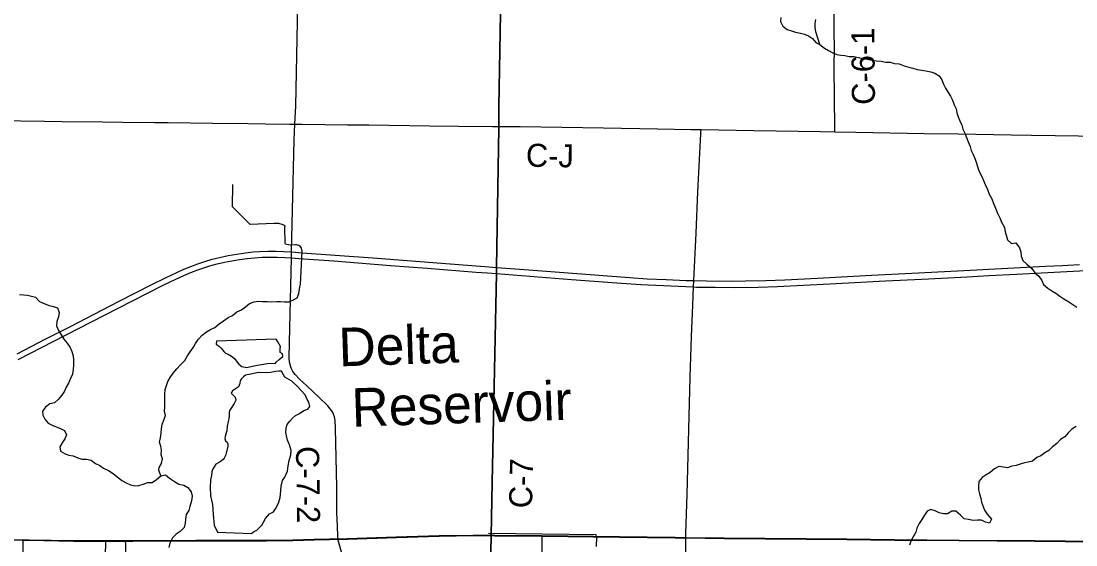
# Model space of a CAD drawing. Extents: x -21.7 to 34, y 0 to 22.
# Drawn here: x 26.522 to 29.12, y 18.47 to 19.76 of the extents above; entities that cross this region are included whole.
import ezdxf

# ---------------------------------------------------------------- set-up
doc = ezdxf.new("R2010")
doc.units = 0
for name, color, linetype in [('GM_X_Corporation', 7, 'Continuous'), ('GM_X_County_Road', 7, 'Continuous'), ('GM_X_County_Road_Text', 7, 'Continuous'), ('GM_X_Interchange_Ramps', 7, 'Continuous'), ('GM_X_Interstate_Route', 7, 'Continuous'), ('GM_X_Minor_Lake', 7, 'Continuous'), ('GM_X_Minor_Lake_Text', 7, 'Continuous'), ('GM_X_Minor_River', 7, 'Continuous'), ('GM_X_Township_Road', 7, 'Continuous')]:
    doc.layers.add(name, color=color, linetype=linetype)

msp = doc.modelspace()

# ---------------------------------------------------------------- linework, layer by layer
at = {"layer": 'GM_X_Corporation'}
for points in [[(26.5248, 17.9802), (26.527, 18.482), (26.7301, 18.4797), (26.7284, 18.4023)], [(27.6767, 18.3342), (27.6799, 18.4934), (27.8047, 18.4919), (27.804, 17.9866)]]:
    msp.add_lwpolyline(points, dxfattribs=at)
at = {"layer": 'GM_X_County_Road'}
for p, q in [((26.7303, 18.4792), (26.7798, 18.4794)), ((27.6769, 18.3336), (27.6801, 18.4929))]:
    msp.add_line(p, q, dxfattribs=at)
for points in [[(27.1963, 19.5062), (27.1964, 19.5073), (27.1988, 19.5508), (27.2033, 19.7591), (27.207, 19.9519), (27.2091, 20.0793), (27.2101, 20.2006), (27.2118, 20.3219), (27.2128, 20.4245), (27.2137, 20.5022), (27.2139, 20.5158)], [(27.6992, 19.5006), (27.6996, 19.5488), (27.7037, 19.7788), (27.7084, 20.0054), (27.7128, 20.2943), (27.7149, 20.4186), (27.7159, 20.4621), (27.717, 20.4952)], [(28.5268, 19.4873), (28.5267, 19.4976), (28.5254, 19.6466), (28.5254, 19.6682), (28.5255, 19.6736), (28.5238, 19.8343), (28.5233, 19.9152), (28.5215, 20.1238), (28.5203, 20.2794), (28.52, 20.376), (28.5193, 20.4694), (28.5191, 20.4734), (28.519, 20.4796), (28.5189, 20.4807)], [(26.433, 19.5159), (26.4618, 19.5156), (26.5799, 19.5136), (26.6235, 19.5132), (26.723, 19.5118), (26.7727, 19.5112), (26.8505, 19.5102), (26.8847, 19.51), (26.9935, 19.509), (27.0806, 19.5079), (27.1241, 19.5072), (27.1832, 19.5062), (27.1963, 19.5062)], [(27.3033, 18.4837), (27.3023, 18.491), (27.3016, 18.5158), (27.3002, 18.5499), (27.3001, 18.5622), (27.2996, 18.6119), (27.2965, 18.7577), (27.2957, 18.7764), (27.294, 18.7858), (27.292, 18.7917), (27.2893, 18.7974), (27.2839, 18.8052), (27.2777, 18.8123), (27.2554, 18.834), (27.2257, 18.8615), (27.2076, 18.8785), (27.197, 18.8897), (27.1916, 18.8971), (27.1874, 18.9053), (27.1855, 18.9111), (27.1836, 18.9201), (27.1829, 18.9324), (27.1841, 19.0039), (27.188, 19.1769), (27.1883, 19.1917), (27.1945, 19.4669), (27.1963, 19.5062)], [(27.1963, 19.5062), (27.2143, 19.506), (27.3262, 19.505), (27.379, 19.5043), (27.4288, 19.5038), (27.5283, 19.5024), (27.5998, 19.5016), (27.6838, 19.5008), (27.6992, 19.5006)], [(27.6801, 18.4929), (27.6827, 18.6228), (27.6932, 19.1383), (27.6935, 19.1534), (27.6992, 19.496), (27.6992, 19.5006)], [(27.6992, 19.5006), (27.7084, 19.5006), (27.7519, 19.5003), (27.9571, 19.497), (28.0907, 19.4945), (28.1716, 19.4934), (28.197, 19.4929)], [(28.1596, 18.4872), (28.1599, 18.4982), (28.1625, 18.5945), (28.1704, 18.8835), (28.1732, 18.983), (28.1766, 19.0605), (28.1787, 19.1054), (28.1794, 19.1211), (28.1848, 19.2375), (28.1895, 19.34), (28.1963, 19.4828), (28.1965, 19.4859), (28.197, 19.4929)], [(28.197, 19.4929), (28.327, 19.4906), (28.4917, 19.4879), (28.5268, 19.4873)], [(28.5268, 19.4873), (28.5787, 19.4865), (28.7466, 19.4836), (28.8305, 19.4824), (28.874, 19.4815), (28.9611, 19.4803), (29.0108, 19.4795), (29.1849, 19.4765), (29.2037, 19.4762)], [(26.4146, 18.4834), (26.4771, 18.4821), (26.5273, 18.4815)], [(26.5273, 18.4815), (26.5424, 18.4813), (26.6512, 18.4792), (26.7009, 18.479), (26.7303, 18.4792)], [(26.7798, 18.4794), (26.7972, 18.4795), (26.9526, 18.4799), (27.0334, 18.4801), (27.0738, 18.4802), (27.1266, 18.4803), (27.1919, 18.4811), (27.2447, 18.4823), (27.282, 18.4832), (27.3033, 18.4837)], [(26.7819, 18.4023), (26.7817, 18.422), (26.7811, 18.4344), (26.78, 18.4717), (26.7798, 18.4794)], [(27.3033, 18.4837), (27.3255, 18.4841), (27.4467, 18.4882), (27.5523, 18.4917), (27.6363, 18.4929), (27.6614, 18.4928), (27.6801, 18.4929)], [(27.3679, 18.2386), (27.3675, 18.2406), (27.3653, 18.2495), (27.3596, 18.2701), (27.3507, 18.3034), (27.3474, 18.3166), (27.3328, 18.3708), (27.3094, 18.4578), (27.3036, 18.4819), (27.3033, 18.4837)], [(27.6801, 18.4929), (27.6889, 18.4927), (27.8049, 18.4914)], [(27.8049, 18.4914), (27.9966, 18.4892), (28.1334, 18.4875), (28.1596, 18.4872)], [(28.153, 17.9846), (28.1531, 17.9926), (28.1537, 18.0454), (28.155, 18.1199), (28.1556, 18.1758), (28.1574, 18.3094), (28.1597, 18.474), (28.1596, 18.4872)], [(28.1596, 18.4872), (28.2546, 18.4861), (28.5561, 18.4831), (28.6742, 18.4819), (28.8328, 18.4806), (29.0193, 18.4793), (29.1704, 18.4779)]]:
    msp.add_lwpolyline(points, dxfattribs=at)
at = {"layer": 'GM_X_Interchange_Ramps'}
for points in [[(26.4769, 18.4826), (26.527, 18.482), (26.5421, 18.4818), (26.6509, 18.4797), (26.7006, 18.4796), (26.7301, 18.4797), (26.7796, 18.4799), (26.797, 18.48), (26.9524, 18.4805), (27.0332, 18.4807), (27.0736, 18.4808), (27.1264, 18.4808), (27.1917, 18.4817), (27.2445, 18.4829), (27.2818, 18.4838), (27.3031, 18.4842), (27.3253, 18.4846), (27.4464, 18.4887), (27.5521, 18.4922), (27.636, 18.4934), (27.6611, 18.4934), (27.6799, 18.4934), (27.6824, 18.6234), (27.6929, 19.1388), (27.6932, 19.154), (27.6989, 19.4965), (27.699, 19.5012), (27.6994, 19.5494), (27.7034, 19.7794)], [(27.7034, 19.7794), (27.6994, 19.5494), (27.699, 19.5012), (27.6989, 19.4965), (27.6932, 19.154), (27.6929, 19.1388), (27.6824, 18.6234), (27.6799, 18.4934), (27.6887, 18.4933), (27.8047, 18.4919), (27.9964, 18.4897), (28.1332, 18.488), (28.1594, 18.4877), (28.2544, 18.4866), (28.5559, 18.4837), (28.674, 18.4825), (28.8325, 18.4812), (29.019, 18.4799), (29.1702, 18.4785)], [(27.6767, 18.3342), (27.6799, 18.4934), (27.6611, 18.4934), (27.636, 18.4934), (27.5521, 18.4922), (27.4464, 18.4887), (27.3253, 18.4846), (27.3031, 18.4842), (27.2818, 18.4838), (27.2445, 18.4829), (27.1917, 18.4817), (27.1264, 18.4808), (27.0736, 18.4808), (27.0332, 18.4807), (26.9524, 18.4805), (26.797, 18.48), (26.7796, 18.4799), (26.7301, 18.4797), (26.7006, 18.4796), (26.6509, 18.4797), (26.5421, 18.4818), (26.527, 18.482), (26.4769, 18.4826)], [(29.1702, 18.4785), (29.019, 18.4799), (28.8325, 18.4812), (28.674, 18.4825), (28.5559, 18.4837), (28.2544, 18.4866), (28.1594, 18.4877), (28.1332, 18.488), (27.9964, 18.4897), (27.8047, 18.4919), (27.6887, 18.4933), (27.6799, 18.4934), (27.6767, 18.3342)]]:
    msp.add_lwpolyline(points, dxfattribs=at)
at = {"layer": 'GM_X_Interstate_Route'}
for points in [[(26.5123, 18.9409), (26.5814, 18.9765), (26.6425, 19.0074), (26.7642, 19.0699), (26.8444, 19.1111), (26.8777, 19.1278), (26.9058, 19.1412), (26.9228, 19.1488), (26.94, 19.1559), (26.9575, 19.1624), (26.9752, 19.1682), (26.9931, 19.1734), (27.0111, 19.178), (27.0323, 19.1826), (27.0537, 19.1864), (27.0752, 19.1895), (27.0938, 19.1915), (27.1092, 19.1926), (27.131, 19.1934), (27.1496, 19.1935), (27.1682, 19.193), (27.1868, 19.1918), (27.1883, 19.1917), (27.2146, 19.1895), (27.3883, 19.1768), (27.5681, 19.163), (27.6642, 19.1556), (27.6935, 19.1534), (27.7727, 19.1476), (28.0208, 19.1285), (28.0642, 19.1257), (28.1108, 19.1233), (28.1605, 19.1215), (28.1794, 19.1211), (28.2103, 19.1204), (28.2756, 19.1199), (28.3067, 19.1202), (28.3565, 19.1214), (28.4031, 19.1231), (28.4838, 19.1271), (28.6173, 19.1346), (28.7167, 19.1392), (28.8285, 19.1451), (28.9682, 19.1522), (29.0459, 19.1562), (29.0862, 19.1585), (29.1297, 19.1605)], [(26.5154, 18.9264), (26.6314, 18.9863), (26.7616, 19.0528), (26.8723, 19.1094), (26.903, 19.1246), (26.9228, 19.1337), (26.94, 19.1409), (26.9575, 19.1476), (26.9723, 19.1526), (26.9872, 19.1572), (27.0052, 19.162), (27.0234, 19.1663), (27.0417, 19.17), (27.0601, 19.1731), (27.0787, 19.1755), (27.0973, 19.1773), (27.1159, 19.1784), (27.1346, 19.1788), (27.1533, 19.1786), (27.172, 19.1779), (27.188, 19.1769), (27.2061, 19.1757), (27.2929, 19.1694), (27.4324, 19.1583), (27.5223, 19.1516), (27.6432, 19.1421), (27.6711, 19.14), (27.6932, 19.1383), (27.8779, 19.124), (27.9897, 19.1154), (28.0488, 19.111), (28.1787, 19.1054), (28.1858, 19.1051), (28.2318, 19.1048), (28.2786, 19.1039), (28.3377, 19.1049), (28.3843, 19.1063), (28.5147, 19.1128), (28.6513, 19.1201), (28.7413, 19.1247), (28.8531, 19.1304), (28.9059, 19.1332), (28.9742, 19.1365), (29.0829, 19.1422), (29.191, 19.148)]]:
    msp.add_lwpolyline(points, dxfattribs=at)
at = {"layer": 'GM_X_Minor_Lake'}
for p, q in [((27.1507, 18.9763), (27.0034, 18.9716)), ((27.0064, 18.5013), (27.0898, 18.4982))]:
    msp.add_line(p, q, dxfattribs=at)
for points in [[(27.0034, 18.9716), (27.0029, 18.9648), (27.0062, 18.9617), (27.0111, 18.9589), (27.0148, 18.9543), (27.0181, 18.9508), (27.0218, 18.9466), (27.0255, 18.9419), (27.0319, 18.9399), (27.0409, 18.9351), (27.0476, 18.9289), (27.052, 18.9231), (27.0582, 18.9154), (27.0661, 18.9095), (27.0782, 18.9073), (27.0953, 18.9111), (27.1285, 18.9165), (27.1486, 18.9179), (27.1502, 18.9198), (27.1583, 18.9268), (27.1668, 18.9338), (27.1658, 18.9407), (27.1606, 18.9442), (27.1601, 18.9533), (27.161, 18.9586), (27.1581, 18.9648), (27.1544, 18.9705), (27.1507, 18.9763)], [(27.0898, 18.4982), (27.0948, 18.5023), (27.1025, 18.5063), (27.1087, 18.5119), (27.1149, 18.5182), (27.1196, 18.5257), (27.124, 18.5347), (27.1345, 18.5466), (27.1441, 18.5517), (27.1492, 18.5584), (27.1564, 18.5731), (27.1601, 18.5866), (27.1617, 18.6037), (27.1631, 18.6147), (27.1664, 18.6283), (27.1719, 18.6369), (27.1788, 18.6519), (27.1802, 18.6648), (27.1828, 18.6776), (27.1869, 18.6916), (27.1875, 18.7022), (27.1833, 18.7163), (27.1786, 18.7278), (27.1762, 18.7389), (27.1742, 18.748), (27.1752, 18.7583), (27.178, 18.7662), (27.1843, 18.7751), (27.1906, 18.7822), (27.1979, 18.7885), (27.2083, 18.794), (27.2187, 18.8006), (27.2283, 18.8045), (27.2337, 18.8109), (27.2313, 18.8219), (27.2269, 18.8285), (27.2219, 18.8396), (27.2123, 18.8504), (27.2038, 18.8597), (27.1893, 18.873), (27.1777, 18.8801), (27.1717, 18.8832), (27.1688, 18.8886), (27.1633, 18.8975), (27.1572, 18.8983), (27.1496, 18.8974), (27.1367, 18.895), (27.1245, 18.8941), (27.1067, 18.8942), (27.0884, 18.8904), (27.0747, 18.8884), (27.0704, 18.8843), (27.0646, 18.878), (27.0618, 18.8739), (27.0609, 18.8679), (27.0593, 18.8637), (27.0581, 18.8592), (27.0527, 18.8563), (27.043, 18.8497), (27.0399, 18.844), (27.0447, 18.8386), (27.0499, 18.8339), (27.0512, 18.8263), (27.0468, 18.8181), (27.0394, 18.8065), (27.0354, 18.8012), (27.0349, 18.7956), (27.0344, 18.7876), (27.0342, 18.7804), (27.0321, 18.7736), (27.0296, 18.7627), (27.0289, 18.7509), (27.0277, 18.746), (27.0248, 18.7369), (27.0239, 18.7317), (27.0257, 18.7267), (27.0302, 18.7228), (27.0316, 18.7178), (27.0315, 18.7136), (27.0289, 18.7016), (27.0277, 18.6966), (27.0268, 18.6917), (27.0224, 18.6835), (27.0201, 18.6805), (27.0123, 18.6746), (27.0023, 18.6687), (26.998, 18.662), (26.9949, 18.6571), (26.992, 18.65), (26.9911, 18.6413), (26.9889, 18.6299), (26.9881, 18.6125), (26.9884, 18.5905), (26.9935, 18.5691), (26.9956, 18.5451), (26.9977, 18.5189), (27.0064, 18.5013)]]:
    msp.add_lwpolyline(points, dxfattribs=at)
at = {"layer": 'GM_X_Minor_River'}
msp.add_line((27.9386, 18.4944), (27.6734, 18.4982), dxfattribs=at)
for points in [[(28.3936, 19.7694), (28.393, 19.7592), (28.3985, 19.7477), (28.4096, 19.7395), (28.4198, 19.7362), (28.4296, 19.733), (28.4417, 19.7305), (28.4518, 19.728), (28.4616, 19.7236), (28.4717, 19.717), (28.4802, 19.7073), (28.49, 19.7022), (28.5012, 19.6932), (28.5109, 19.6877), (28.5218, 19.6822), (28.5319, 19.6782), (28.5417, 19.6761), (28.5516, 19.6751), (28.5617, 19.673), (28.5731, 19.6732), (28.5852, 19.6706), (28.5954, 19.6682), (28.6071, 19.666), (28.6176, 19.6643), (28.6293, 19.6625), (28.6411, 19.6612), (28.652, 19.6587), (28.663, 19.6592), (28.6739, 19.6559), (28.6853, 19.6546), (28.6977, 19.6501), (28.7093, 19.6465), (28.7191, 19.644), (28.7297, 19.6411), (28.741, 19.6394), (28.7508, 19.6377), (28.7629, 19.6352), (28.7731, 19.6315), (28.7835, 19.6253), (28.7905, 19.6156), (28.7941, 19.6049), (28.7996, 19.5953), (28.8058, 19.5846), (28.8117, 19.5749), (28.8164, 19.565), (28.8204, 19.5539), (28.8251, 19.5443), (28.8272, 19.534), (28.8304, 19.5244), (28.8343, 19.5141), (28.8394, 19.5038), (28.8423, 19.4942), (28.847, 19.4839), (28.8506, 19.4732), (28.8553, 19.4624), (28.8596, 19.4513), (28.8628, 19.4418), (28.8675, 19.4314), (28.8726, 19.4199), (28.8754, 19.4104), (28.8801, 19.3966), (28.884, 19.3867), (28.8888, 19.3771), (28.8927, 19.3675), (28.8971, 19.3579), (28.9029, 19.3457), (28.9072, 19.3338), (28.913, 19.3227), (28.9174, 19.3108), (28.9221, 19.2997), (28.9275, 19.2871), (28.9329, 19.2756), (28.9373, 19.2645), (28.9442, 19.2514), (28.9459, 19.2407), (28.9495, 19.2308), (28.9519, 19.2213), (28.962, 19.2127), (28.9722, 19.2136), (28.9814, 19.2017), (28.9847, 19.1917), (28.986, 19.1815), (28.9899, 19.1708), (28.9999, 19.1611), (29.0115, 19.1506), (29.0189, 19.1405), (29.0293, 19.1316), (29.0363, 19.1216), (29.0406, 19.1116), (29.0514, 19.1023), (29.0611, 19.0957), (29.0712, 19.0898), (29.0809, 19.0823), (29.0907, 19.0757)], [(28.49, 19.7022), (28.4796, 19.7335), (28.4779, 19.7442), (28.4781, 19.7541), (28.4795, 19.7643)], [(27.2101, 19.1113), (27.2143, 19.1943), (27.2119, 19.2027), (27.2089, 19.2062), (27.2006, 19.2094), (27.1978, 19.2089), (27.1847, 19.2082), (27.1771, 19.2096), (27.1737, 19.2108), (27.1727, 19.2138), (27.1717, 19.2514), (27.1725, 19.2556), (27.168, 19.2587), (27.1575, 19.2616), (27.1453, 19.2619), (27.0865, 19.259), (27.0431, 19.3025), (27.044, 19.3579)], [(26.8666, 18.6403), (26.8618, 18.6544), (26.8625, 18.6605), (26.8677, 18.6706), (26.8706, 18.6819), (26.8674, 18.6915), (26.8681, 18.7036), (26.8661, 18.7135), (26.8632, 18.7231), (26.8658, 18.7337), (26.8676, 18.745), (26.8678, 18.756), (26.8696, 18.767), (26.874, 18.7775), (26.8781, 18.7888), (26.8757, 18.7995), (26.8759, 18.8097), (26.8766, 18.8207), (26.8764, 18.8302), (26.8763, 18.8412), (26.8769, 18.8526), (26.8802, 18.8624), (26.8835, 18.8726), (26.8894, 18.8827), (26.8968, 18.8928), (26.9058, 18.9036), (26.9152, 18.9136), (26.9253, 18.9244), (26.932, 18.9357), (26.9387, 18.9454), (26.9465, 18.9566), (26.9521, 18.9663), (26.9591, 18.9764), (26.9681, 18.9865), (26.9786, 18.995), (26.9889, 19.0004), (26.9997, 19.0055), (27.0098, 19.0148), (27.0205, 19.0217), (27.0321, 19.0298), (27.0429, 19.0353), (27.0537, 19.0442), (27.0648, 19.0492), (27.0749, 19.0566), (27.0849, 19.0647), (27.096, 19.0686), (27.1063, 19.0703), (27.1169, 19.0693), (27.1291, 19.0698), (27.1396, 19.0688), (27.1518, 19.0697), (27.1613, 19.0698), (27.1711, 19.0689), (27.1814, 19.0686), (27.1917, 19.0726), (27.2025, 19.0788), (27.2061, 19.089), (27.2079, 19.0999), (27.21, 19.1097), (27.2101, 19.1113)], [(26.5182, 19.0869), (26.5281, 19.0863), (26.5383, 19.0849), (26.5481, 19.0828), (26.5579, 19.0799), (26.5679, 19.0698), (26.5803, 19.0635), (26.5912, 19.0598), (26.6017, 19.0569), (26.6119, 19.054), (26.6158, 19.0422), (26.6144, 19.032), (26.6104, 19.0199), (26.6094, 19.0097), (26.6144, 18.9982), (26.621, 18.9874), (26.6279, 18.977), (26.636, 18.9669), (26.643, 18.9562), (26.6473, 18.9466), (26.6505, 18.9359), (26.6517, 18.9248), (26.6515, 18.9131), (26.6501, 18.9021), (26.6487, 18.8907), (26.6442, 18.8798), (26.639, 18.8682), (26.6331, 18.8584), (26.6291, 18.8487), (26.6228, 18.8386), (26.6138, 18.8281), (26.6041, 18.8196), (26.5934, 18.8172), (26.5826, 18.8091), (26.5748, 18.7994), (26.5757, 18.7895), (26.5808, 18.7799), (26.5885, 18.7699), (26.5986, 18.7647), (26.6088, 18.7611), (26.6197, 18.757), (26.6294, 18.7519), (26.6337, 18.7411), (26.6301, 18.7313), (26.6238, 18.7216), (26.6175, 18.7115), (26.6195, 18.7005), (26.6304, 18.6941), (26.6402, 18.6913), (26.6504, 18.6895), (26.662, 18.6847), (26.6722, 18.6814), (26.6836, 18.6812), (26.6949, 18.679), (26.7057, 18.6708), (26.7158, 18.6653), (26.7255, 18.659), (26.7379, 18.653), (26.7491, 18.6459), (26.7707, 18.6288), (26.7808, 18.6228), (26.7921, 18.618), (26.8026, 18.6151), (26.8122, 18.6161), (26.8232, 18.6192), (26.8343, 18.6235), (26.8454, 18.624), (26.8558, 18.631), (26.8666, 18.6403), (26.8777, 18.6427), (26.8877, 18.6345), (26.9004, 18.6262), (26.9109, 18.6195), (26.923, 18.6174), (26.9331, 18.6115), (26.9415, 18.6003)], [(29.0907, 19.0757), (29.1004, 19.0706), (29.1127, 19.0623), (29.1225, 19.0553)], [(29.1211, 18.7618), (29.1107, 18.7548), (29.101, 18.7459), (29.0933, 18.7362), (29.0821, 18.7292), (29.0732, 18.7195), (29.0632, 18.7113), (29.0536, 18.7024), (29.0436, 18.6969), (29.034, 18.6895), (29.0244, 18.6852), (29.0133, 18.6763), (29.003, 18.6734), (28.9935, 18.6717), (28.9835, 18.6685), (28.9736, 18.6657), (28.9626, 18.6636), (28.9523, 18.6597), (28.9421, 18.6614), (28.9304, 18.6628), (28.9197, 18.6577), (28.9096, 18.6484), (28.8997, 18.6429), (28.8897, 18.6362), (28.8815, 18.6265), (28.8802, 18.6155), (28.8804, 18.606), (28.8832, 18.5957), (28.886, 18.585), (28.8881, 18.5751), (28.8953, 18.5552), (28.9015, 18.5456), (28.9126, 18.5336), (28.9075, 18.5239), (28.8977, 18.526), (28.8876, 18.5311), (28.8777, 18.5309), (28.8675, 18.53), (28.8562, 18.5329), (28.8456, 18.5342), (28.8359, 18.5428), (28.8247, 18.5529), (28.8149, 18.5527), (28.8042, 18.5468), (28.7939, 18.5463), (28.7834, 18.5488), (28.7736, 18.5535), (28.7635, 18.5571), (28.7539, 18.5532), (28.7476, 18.543), (28.7406, 18.5322), (28.7343, 18.5224), (28.7288, 18.5115), (28.726, 18.5013), (28.7193, 18.4901), (28.7142, 18.4795), (28.7105, 18.4697)], [(26.9415, 18.6003), (26.944, 18.59), (26.9422, 18.5782), (26.938, 18.5647), (26.9355, 18.5545), (26.9288, 18.5447), (26.9271, 18.5334), (26.9261, 18.5235), (26.9243, 18.5126), (26.9142, 18.5029), (26.9046, 18.4967), (26.8949, 18.487), (26.8889, 18.4739), (26.8863, 18.4637)], [(27.9399, 18.4663), (27.9403, 18.4883), (27.9386, 18.4944)]]:
    msp.add_lwpolyline(points, dxfattribs=at)
at = {"layer": 'GM_X_Township_Road'}
for points in [[(26.433, 19.5159), (26.4618, 19.5156), (26.5799, 19.5136), (26.6235, 19.5132), (26.723, 19.5118), (26.7727, 19.5112), (26.8505, 19.5102), (26.8847, 19.51), (26.9935, 19.509), (27.0806, 19.5079), (27.1241, 19.5072), (27.1832, 19.5062), (27.1963, 19.5062)], [(27.1963, 19.5062), (27.2143, 19.506), (27.3262, 19.505), (27.379, 19.5043), (27.4288, 19.5038), (27.5283, 19.5024), (27.5998, 19.5016), (27.6838, 19.5008), (27.6992, 19.5006)], [(27.6992, 19.5006), (27.7084, 19.5006), (27.7519, 19.5003), (27.9571, 19.497), (28.0907, 19.4945), (28.1716, 19.4934), (28.197, 19.4929)], [(28.197, 19.4929), (28.327, 19.4906), (28.4917, 19.4879), (28.5268, 19.4873)], [(28.5268, 19.4873), (28.5787, 19.4865), (28.7466, 19.4836), (28.8305, 19.4824), (28.874, 19.4815), (28.9611, 19.4803), (29.0108, 19.4795), (29.1849, 19.4765), (29.2037, 19.4762)]]:
    msp.add_lwpolyline(points, dxfattribs=at)

# ---------------------------------------------------------------- texts
at = {"layer": 'GM_X_County_Road_Text'}
for s, rotation, p in [('C-6-1', 90.5851, (28.6257, 19.5542)), ('C-J', 359.0128, (27.7653, 19.4016)), ('C-7-2', 270.8839, (27.1992, 18.7129)), ('C-7', 88.6291, (27.7807, 18.5597))]:
    msp.add_text(s, height=0.05682, rotation=rotation, dxfattribs=at).set_placement(p)
at = {"layer": 'GM_X_Minor_Lake_Text'}
for s, rotation, p in [('Delta', 1.8965, (27.3058, 18.9096)), ('Reservoir', 1.8967, (27.3379, 18.7608))]:
    msp.add_text(s, height=0.09476, rotation=rotation, dxfattribs=at).set_placement(p)

doc.saveas('drawing.dxf')
